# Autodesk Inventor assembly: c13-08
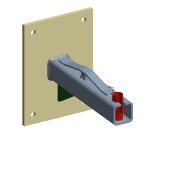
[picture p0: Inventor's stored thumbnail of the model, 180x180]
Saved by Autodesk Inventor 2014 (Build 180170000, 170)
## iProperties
Created: 2011-01
Part Number: c13-08
Document SubType Name: Weldment
Designer: Thom Tremblay
Weld Material: Welded Steel Mild
_SolveAssemblyDoc: Frame Generator Solve Assembly
_Version: 15.0.0
Author: Thom Tremblay
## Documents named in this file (5)
- C:\Inventor 2014 Essentials\Assemblies\Chapter 13\c13-08.iam
- C:\Inventor 2014 Essentials\Parts\Chapter 13\c13-01.ipt
- C:\Inventor 2014 Essentials\Parts\Chapter 13\c13-02.ipt
- C:\Inventor 2014 Essentials\Assemblies\Chapter 13\Frame\Frame c13-01.iam
- C:\Inventor 2014 Essentials\Parts\Chapter 13\c13-03.ipt
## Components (4 placed, 4 different names)
1. c13-01:1 — Mate:2
2. c13-02:1 — Flush:1
3. Frame c13-01:1 [sub-assembly] — Mate:3
4. c13-03:1 — Mate:1, Mate:2, Mate:3
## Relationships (4: Mate 3, Flush 1)
- Flush:1: c13-02:1
- Mate:1: c13-03:1
- Mate:2: c13-01:1 ↔ c13-03:1
- Mate:3: Frame c13-01:1 ↔ c13-03:1
